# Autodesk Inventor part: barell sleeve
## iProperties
Created: 2006-04
Part Number: barell sleeve
Document SubType Name: Modeling
Designer: Калинин
Author: Калинин
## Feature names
1. Выдавливание1 [Extrusion]
2. Отверстие1 [Hole]
3. Выдавливание2 [Extrusion]
4. Выдавливание3 [Extrusion]
5. Выдавливание4 [Extrusion]
6. Выдавливание5 [Extrusion]
7. Круговой массив1 [Circular Pattern]
8. Выдавливание6 [Extrusion]
9. Круговой массив2 [Circular Pattern]
10. Фаска1 [Chamfer]
11. Сопряжение1 [Fillet]
12. Сопряжение2 [Fillet]
13. Сопряжение3 [Fillet]
14. Сопряжение4 [Fillet]
15. Сопряжение5 [Fillet]
16. Сопряжение6 [Fillet]
